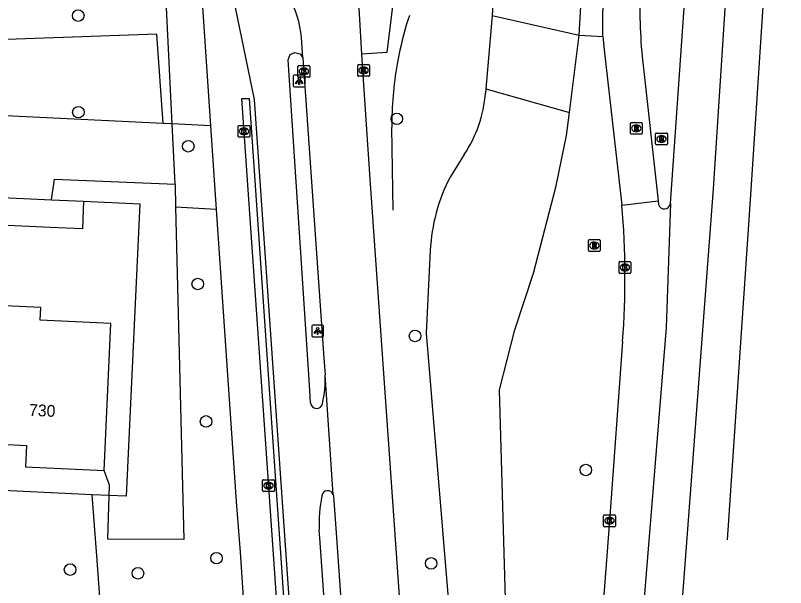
# Model space of a CAD drawing. Extents: x 161253 to 161848, y 384872 to 385383.
# Drawn here: x 161781 to 161846.3, y 385306.2 to 385354.7 of the extents above; entities that cross this region are included whole.
import ezdxf

# ---------------------------------------------------------------- set-up
doc = ezdxf.new("R2010")
doc.units = 0
for name, color, linetype in [('IMGEO_Berm_groen', 7, 'Continuous'), ('IMGEO_Boom', 7, 'Continuous'), ('IMGEO_Fietspad_open', 7, 'Continuous'), ('IMGEO_Groenvoorziening', 7, 'Continuous'), ('IMGEO_Hek', 7, 'Continuous'), ('IMGEO_Kolk', 7, 'Continuous'), ('IMGEO_Lichtpunt', 7, 'Continuous'), ('IMGEO_Muur', 7, 'Continuous'), ('IMGEO_Pand', 7, 'Continuous'), ('IMGEO_Pand_nummerreeks', 7, 'Continuous'), ('IMGEO_Rijbaan_lokaal_open', 7, 'Continuous'), ('IMGEO_Rijbaan_regionaal_gesloten', 7, 'Continuous'), ('IMGEO_Rioolput', 7, 'Continuous'), ('IMGEO_Voetpad_open', 7, 'Continuous')]:
    doc.layers.add(name, color=color, linetype=linetype)

msp = doc.modelspace()

# ---------------------------------------------------------------- linework, layer by layer
at = {"layer": 'IMGEO_Berm_groen'}
for points in [[(161820.751, 385357.276), (161820.788, 385357.005), (161821.547, 385357.044), (161821.412, 385354.663)], [(161821.412, 385354.663), (161820.884, 385348.462)], [(161821.412, 385354.663), (161828.775, 385352.994)], [(161827.957, 385346.444), (161828.775, 385352.994)], [(161820.884, 385348.462), (161820.852, 385348.089)], [(161820.884, 385348.462), (161827.957, 385346.444)], [(161816.166, 385334.74), (161815.82, 385327.746), (161822.257, 385250), (161823.001, 385241.01), (161823.031, 385250), (161823.145, 385284.452), (161822.02, 385322.916), (161823.326, 385328.009), (161824.925, 385332.823), (161826.852, 385340.216), (161827.714, 385344.496), (161827.957, 385346.444)], [(161819.046, 385342.871), (161817.837, 385340.968)]]:
    msp.add_lwpolyline(points, dxfattribs=at)
for centre, radius, start, end in [((161809.645, 385349.046), 11.248, 326.70052, 355.11703), ((161831.326, 385334.011), 15.178, 152.71653, 177.2455)]:
    msp.add_arc(centre, radius, start, end, dxfattribs=at)
at = {"layer": 'IMGEO_Boom'}
for centre in [(161786.31, 385354.662), (161786.323, 385346.475), (161813.332, 385345.903), (161795.642, 385343.583), (161796.445, 385331.904), (161814.873, 385327.495), (161797.146, 385320.249), (161829.357, 385316.131), (161798.038, 385308.659), (161816.236, 385308.211), (161785.619, 385307.682), (161791.373, 385307.373)]:
    msp.add_circle(centre, 0.489, dxfattribs=at)
at = {"layer": 'IMGEO_Fietspad_open'}
for points in [[(161799.416, 385136.747), (161804.851, 385161.932), (161805.798, 385165.717), (161808.364, 385173.407), (161809.023, 385177.396), (161809.973, 385187.32), (161810.725, 385197.446), (161810.795, 385201.149), (161811.014, 385207.171), (161808.054, 385250), (161801.247, 385347.561), (161799.482, 385356.188)], [(161806.008, 385321.812), (161805.94, 385322.912), (161804.115, 385350.912), (161804.294, 385351.353), (161804.687, 385351.542), (161805.133, 385351.414), (161805.369, 385351.08)], [(161806.85, 385157.128), (161812.029, 385175.625), (161814.159, 385203.908), (161813.652, 385212.427), (161806.814, 385309.979), (161806.751, 385311.045)]]:
    msp.add_lwpolyline(points, dxfattribs=at)
for centre, radius, start, end in [((161798.01, 385323.776), 9.239, 347.4358, 2.69956), ((161806.521, 385321.865), 0.516, 185.84527, 348.99038), ((161807.47, 385313.88), 0.496, 20.6567, 172.69349), ((161816.86, 385311.711), 10.131, 167.2724, 183.76995)]:
    msp.add_arc(centre, radius, start, end, dxfattribs=at)
at = {"layer": 'IMGEO_Groenvoorziening'}
for points in [[(161794.271, 385345.479), (161793.707, 385357.113)], [(161793.503, 385345.516), (161792.985, 385353.084), (161763.52, 385352.051), (161763.273, 385346.984)], [(161793.503, 385345.516), (161763.273, 385346.984)], [(161794.271, 385345.479), (161793.503, 385345.516)], [(161794.518, 385340.375), (161794.271, 385345.479)], [(161797.526, 385345.32), (161794.271, 385345.479)], [(161784.036, 385339.05), (161784.298, 385340.786), (161794.518, 385340.375)], [(161794.518, 385340.375), (161794.566, 385338.411)], [(161786.764, 385338.926), (161791.529, 385338.709), (161790.371, 385313.925), (161788.928, 385313.964)], [(161794.566, 385338.411), (161795.257, 385310.23), (161788.827, 385310.268), (161788.928, 385313.964)], [(161798.011, 385338.225), (161794.566, 385338.411)], [(161788.928, 385313.964), (161787.504, 385314.033)]]:
    msp.add_lwpolyline(points, dxfattribs=at)
at = {"layer": 'IMGEO_Hek'}
for points in [[(161813.495, 385351.313), (161813.349, 385350.542)], [(161813.007, 385338.149), (161812.908, 385345.182)], [(161784.036, 385339.05), (161784.298, 385340.786), (161794.518, 385340.375)], [(161794.518, 385340.375), (161794.566, 385338.411)], [(161794.566, 385338.411), (161795.257, 385310.23), (161788.827, 385310.268), (161788.928, 385313.964)], [(161788.928, 385313.964), (161788.952, 385314.831), (161788.498, 385316.088)]]:
    msp.add_lwpolyline(points, dxfattribs=at)
for centre, radius, start, end in [((161842.19, 385345.507), 29.276, 161.74486, 168.56194), ((161842.385, 385345.455), 29.478, 170.06258, 180.53046)]:
    msp.add_arc(centre, radius, start, end, dxfattribs=at)
at = {"layer": 'IMGEO_Kolk'}
for p, q in [((161804.945, 385349.501), (161804.945, 385350.353)), ((161805.02, 385350.427), (161805.872, 385350.427)), ((161805.433, 385350.207), (161805.458, 385350.207)), ((161805.946, 385350.353), (161805.946, 385349.501)), ((161810.007, 385349.586), (161810.007, 385350.438)), ((161810.082, 385350.512), (161810.934, 385350.512)), ((161810.495, 385350.292), (161810.52, 385350.292)), ((161811.008, 385350.438), (161811.008, 385349.586)), ((161805.456, 385349.647), (161805.431, 385349.647)), ((161810.518, 385349.732), (161810.493, 385349.732)), ((161805.872, 385349.427), (161805.02, 385349.427)), ((161810.934, 385349.512), (161810.082, 385349.512)), ((161799.866, 385344.421), (161799.866, 385345.273)), ((161799.941, 385345.347), (161800.793, 385345.347)), ((161800.354, 385345.127), (161800.379, 385345.127)), ((161800.867, 385345.273), (161800.867, 385344.421)), ((161800.793, 385344.347), (161799.941, 385344.347)), ((161800.377, 385344.567), (161800.352, 385344.567)), ((161832.167, 385332.875), (161832.167, 385333.727)), ((161832.242, 385333.801), (161833.094, 385333.801)), ((161832.655, 385333.581), (161832.68, 385333.581)), ((161833.168, 385333.727), (161833.168, 385332.875)), ((161833.094, 385332.801), (161832.242, 385332.801)), ((161832.678, 385333.021), (161832.653, 385333.021)), ((161801.943, 385314.383), (161801.943, 385315.235)), ((161802.018, 385315.309), (161802.87, 385315.309)), ((161802.431, 385315.089), (161802.456, 385315.089)), ((161802.944, 385315.235), (161802.944, 385314.383)), ((161802.87, 385314.309), (161802.018, 385314.309)), ((161802.454, 385314.529), (161802.429, 385314.529)), ((161830.932, 385312.324), (161831.784, 385312.324)), ((161830.857, 385311.398), (161830.857, 385312.25)), ((161831.345, 385312.104), (161831.37, 385312.104)), ((161831.858, 385312.25), (161831.858, 385311.398)), ((161831.784, 385311.324), (161830.932, 385311.324)), ((161831.368, 385311.544), (161831.343, 385311.544))]:
    msp.add_line(p, q, dxfattribs=at)
for points in [[(161804.945, 385349.501), (161804.945, 385350.353)], [(161805.02, 385350.427), (161805.872, 385350.427)], [(161805.946, 385350.353), (161805.946, 385349.501)], [(161810.007, 385349.586), (161810.007, 385350.438)], [(161810.082, 385350.512), (161810.934, 385350.512)], [(161810.328, 385350.212), (161810.451, 385350.212), (161810.451, 385350.061), (161810.581, 385350.212), (161810.745, 385350.212), (161810.599, 385350.061), (161810.752, 385349.812), (161810.6, 385349.812), (161810.515, 385349.976), (161810.451, 385349.909), (161810.451, 385349.812), (161810.328, 385349.812), (161810.328, 385350.212)], [(161811.008, 385350.438), (161811.008, 385349.586)], [(161805.266, 385350.127), (161805.389, 385350.127), (161805.389, 385349.976), (161805.519, 385350.127), (161805.683, 385350.127), (161805.537, 385349.976), (161805.69, 385349.727), (161805.538, 385349.727), (161805.453, 385349.891), (161805.389, 385349.824), (161805.389, 385349.727), (161805.266, 385349.727), (161805.266, 385350.127)], [(161805.872, 385349.427), (161805.02, 385349.427)], [(161810.934, 385349.512), (161810.082, 385349.512)], [(161799.866, 385344.421), (161799.866, 385345.273)], [(161799.941, 385345.347), (161800.793, 385345.347)], [(161800.187, 385345.047), (161800.31, 385345.047), (161800.31, 385344.896), (161800.44, 385345.047), (161800.604, 385345.047), (161800.458, 385344.896), (161800.611, 385344.647), (161800.459, 385344.647), (161800.374, 385344.811), (161800.31, 385344.744), (161800.31, 385344.647), (161800.187, 385344.647), (161800.187, 385345.047)], [(161800.867, 385345.273), (161800.867, 385344.421)], [(161800.793, 385344.347), (161799.941, 385344.347)], [(161832.167, 385332.875), (161832.167, 385333.727)], [(161832.242, 385333.801), (161833.094, 385333.801)], [(161832.488, 385333.501), (161832.611, 385333.501), (161832.611, 385333.35), (161832.741, 385333.501), (161832.905, 385333.501), (161832.759, 385333.35), (161832.912, 385333.101), (161832.76, 385333.101), (161832.675, 385333.265), (161832.611, 385333.198), (161832.611, 385333.101), (161832.488, 385333.101), (161832.488, 385333.501)], [(161833.168, 385333.727), (161833.168, 385332.875)], [(161833.094, 385332.801), (161832.242, 385332.801)], [(161801.943, 385314.383), (161801.943, 385315.235)], [(161802.018, 385315.309), (161802.87, 385315.309)], [(161802.264, 385315.009), (161802.387, 385315.009), (161802.387, 385314.858), (161802.517, 385315.009), (161802.681, 385315.009), (161802.535, 385314.858), (161802.688, 385314.609), (161802.536, 385314.609), (161802.451, 385314.773), (161802.387, 385314.706), (161802.387, 385314.609), (161802.264, 385314.609), (161802.264, 385315.009)], [(161802.944, 385315.235), (161802.944, 385314.383)], [(161802.87, 385314.309), (161802.018, 385314.309)], [(161830.932, 385312.324), (161831.784, 385312.324)], [(161830.857, 385311.398), (161830.857, 385312.25)], [(161831.178, 385312.024), (161831.301, 385312.024), (161831.301, 385311.873), (161831.431, 385312.024), (161831.595, 385312.024), (161831.449, 385311.873), (161831.602, 385311.624), (161831.45, 385311.624), (161831.365, 385311.788), (161831.301, 385311.721), (161831.301, 385311.624), (161831.178, 385311.624), (161831.178, 385312.024)], [(161831.858, 385312.25), (161831.858, 385311.398)], [(161831.784, 385311.324), (161830.932, 385311.324)]]:
    msp.add_lwpolyline(points, dxfattribs=at)
for centre, start, end in [((161805.022, 385350.351), 91.55205, 178.44795), ((161805.022, 385350.351), 91.55205, 178.44795), ((161805.87, 385350.351), 1.55205, 88.44795), ((161805.87, 385350.351), 1.55205, 88.44795), ((161810.084, 385350.436), 91.55205, 178.44795), ((161810.084, 385350.436), 91.55205, 178.44795), ((161810.932, 385350.436), 1.55205, 88.44795), ((161810.932, 385350.436), 1.55205, 88.44795), ((161810.084, 385349.588), 181.55205, 268.44795), ((161810.084, 385349.588), 181.55205, 268.44795), ((161810.932, 385349.588), 271.55205, 358.44795), ((161810.932, 385349.588), 271.55205, 358.44795), ((161805.022, 385349.503), 181.55205, 268.44795), ((161805.022, 385349.503), 181.55205, 268.44795), ((161805.87, 385349.503), 271.55205, 358.44795), ((161805.87, 385349.503), 271.55205, 358.44795), ((161799.943, 385345.271), 91.55205, 178.44795), ((161799.943, 385345.271), 91.55205, 178.44795), ((161800.791, 385345.271), 1.55205, 88.44795), ((161800.791, 385345.271), 1.55205, 88.44795), ((161799.943, 385344.423), 181.55205, 268.44795), ((161799.943, 385344.423), 181.55205, 268.44795), ((161800.791, 385344.423), 271.55205, 358.44795), ((161800.791, 385344.423), 271.55205, 358.44795), ((161832.244, 385333.725), 91.55205, 178.44795), ((161832.244, 385333.725), 91.55205, 178.44795), ((161833.092, 385333.725), 1.55205, 88.44795), ((161833.092, 385333.725), 1.55205, 88.44795), ((161832.244, 385332.877), 181.55205, 268.44795), ((161832.244, 385332.877), 181.55205, 268.44795), ((161833.092, 385332.877), 271.55205, 358.44795), ((161833.092, 385332.877), 271.55205, 358.44795), ((161802.02, 385315.233), 91.55205, 178.44795), ((161802.02, 385315.233), 91.55205, 178.44795), ((161802.868, 385315.233), 1.55205, 88.44795), ((161802.868, 385315.233), 1.55205, 88.44795), ((161802.02, 385314.385), 181.55205, 268.44795), ((161802.02, 385314.385), 181.55205, 268.44795), ((161802.868, 385314.385), 271.55205, 358.44795), ((161802.868, 385314.385), 271.55205, 358.44795), ((161830.934, 385312.248), 91.55205, 178.44795), ((161830.934, 385312.248), 91.55205, 178.44795), ((161831.782, 385312.248), 1.55205, 88.44795), ((161831.782, 385312.248), 1.55205, 88.44795), ((161830.934, 385311.4), 181.55205, 268.44795), ((161830.934, 385311.4), 181.55205, 268.44795), ((161831.782, 385311.4), 271.55205, 358.44795), ((161831.782, 385311.4), 271.55205, 358.44795)]:
    msp.add_arc(centre, 0.0765, start, end, dxfattribs=at)
for centre, major_axis, ratio, start_param, end_param in [((161805.432, 385349.927), (-0.387, 0.002), 0.722429, 4.712389, 7.853982), ((161805.457, 385349.927), (-0.39, 0.002), 0.717154, 1.570796, 4.712389), ((161810.494, 385350.012), (-0.387, 0.002), 0.722429, 4.712389, 7.853982), ((161810.519, 385350.012), (-0.39, 0.002), 0.717154, 1.570796, 4.712389), ((161800.353, 385344.847), (-0.387, 0.002), 0.722429, 4.712389, 7.853982), ((161800.378, 385344.847), (-0.39, 0.002), 0.717154, 1.570796, 4.712389), ((161832.654, 385333.301), (-0.387, 0.002), 0.722429, 4.712389, 7.853982), ((161832.679, 385333.301), (-0.39, 0.002), 0.717154, 1.570796, 4.712389), ((161802.43, 385314.809), (-0.387, 0.002), 0.722429, 4.712389, 7.853982), ((161802.455, 385314.809), (-0.39, 0.002), 0.717154, 1.570796, 4.712389), ((161831.344, 385311.824), (-0.387, 0.002), 0.722429, 4.712389, 7.853982), ((161831.369, 385311.824), (-0.39, 0.002), 0.717154, 1.570796, 4.712389)]:
    msp.add_ellipse(centre, major_axis=major_axis, ratio=ratio, start_param=start_param, end_param=end_param, dxfattribs=at)
at = {"layer": 'IMGEO_Lichtpunt'}
for p, q in [((161805.451, 385349.607), (161804.643, 385349.607)), ((161805.451, 385349.607), (161804.643, 385349.607)), ((161804.549, 385349.512), (161804.549, 385348.705)), ((161804.549, 385349.512), (161804.549, 385348.705)), ((161805.545, 385348.705), (161805.545, 385349.512)), ((161805.545, 385348.705), (161805.545, 385349.512)), ((161804.643, 385348.611), (161805.451, 385348.611)), ((161804.643, 385348.611), (161805.451, 385348.611)), ((161806.117, 385328.329), (161806.117, 385327.522)), ((161806.117, 385328.329), (161806.117, 385327.522)), ((161807.019, 385328.424), (161806.211, 385328.424)), ((161807.019, 385328.424), (161806.211, 385328.424)), ((161807.113, 385327.522), (161807.113, 385328.329)), ((161807.113, 385327.522), (161807.113, 385328.329)), ((161806.211, 385327.428), (161807.019, 385327.428)), ((161806.211, 385327.428), (161807.019, 385327.428))]:
    msp.add_line(p, q, dxfattribs=at)
for points in [[(161804.923, 385349.176), (161804.962, 385349.148), (161804.774, 385348.886), (161804.736, 385348.913), (161804.923, 385349.176)], [(161805.025, 385349.128), (161805.072, 385349.128), (161805.072, 385348.806), (161805.025, 385348.806), (161805.025, 385349.128)], [(161805.135, 385349.148), (161805.173, 385349.175), (161805.36, 385348.913), (161805.321, 385348.885), (161805.135, 385349.148)], [(161806.491, 385327.993), (161806.53, 385327.965), (161806.342, 385327.703), (161806.304, 385327.73), (161806.491, 385327.993)], [(161806.703, 385327.965), (161806.741, 385327.992), (161806.928, 385327.73), (161806.889, 385327.702), (161806.703, 385327.965)], [(161806.593, 385327.945), (161806.64, 385327.945), (161806.64, 385327.623), (161806.593, 385327.623), (161806.593, 385327.945)]]:
    msp.add_lwpolyline(points, dxfattribs=at)
for centre in [(161805.048, 385349.31), (161806.616, 385328.127)]:
    msp.add_circle(centre, 0.0994, dxfattribs=at)
for centre, start, end in [((161804.643, 385349.512), 90, 180), ((161804.643, 385349.512), 90, 180), ((161805.451, 385349.512), 0, 90), ((161805.451, 385349.512), 0, 90), ((161804.643, 385348.705), 180, 270), ((161804.643, 385348.705), 180, 270), ((161805.451, 385348.705), 270, 0), ((161805.451, 385348.705), 270, 360), ((161806.211, 385328.329), 90, 180), ((161806.211, 385328.329), 90, 180), ((161807.019, 385328.329), 0, 90), ((161807.019, 385328.329), 0, 90), ((161806.211, 385327.522), 180, 270), ((161806.211, 385327.522), 180, 270), ((161807.019, 385327.522), 270, 0), ((161807.019, 385327.522), 270, 360)]:
    msp.add_arc(centre, 0.0946, start, end, dxfattribs=at)
at = {"layer": 'IMGEO_Muur'}
msp.add_lwpolyline([(161809.266, 385191.488), (161809.957, 385207.224), (161806.977, 385250), (161800.175, 385347.621), (161800.798, 385347.634), (161807.52, 385250), (161810.465, 385207.275), (161809.778, 385192.126), (161808.589, 385177.868), (161808.119, 385177.946)], dxfattribs=at)
at = {"layer": 'IMGEO_Pand'}
for points in [[(161779.237, 385339.268), (161784.036, 385339.05)], [(161786.764, 385338.926), (161786.658, 385336.573), (161783.93, 385336.696), (161779.117, 385336.914)], [(161784.036, 385339.05), (161786.764, 385338.926)], [(161778.178, 385318.394), (161781.911, 385318.22), (161781.826, 385316.4), (161788.498, 385316.088), (161789.079, 385328.549), (161783.08, 385328.829), (161783.131, 385329.911), (161778.88, 385330.109), (161778.733, 385326.946), (161778.612, 385326.952)]]:
    msp.add_lwpolyline(points, dxfattribs=at)
at = {"layer": 'IMGEO_Rijbaan_lokaal_open'}
for points in [[(161830.805, 385352.903), (161830.796, 385354.908), (161830.841, 385355.738), (161830.948, 385357.532), (161831.064, 385359.484), (161831.194, 385361.662), (161831.255, 385362.69), (161831.469, 385366.284), (161831.665, 385369.572), (161831.718, 385370.476), (161831.736, 385370.773), (161832.059, 385376.203), (161832.368, 385380.807), (161832.388, 385381.111), (161832.439, 385381.868), (161832.509, 385382.906)], [(161830.805, 385352.903), (161830.939, 385351.516), (161832.415, 385338.59)], [(161834.125, 385351.188), (161835.492, 385338.948)]]:
    msp.add_lwpolyline(points, dxfattribs=at)
msp.add_arc((161879.572, 385355.321), 45.635, 177.02342, 185.19659, dxfattribs=at)
at = {"layer": 'IMGEO_Rijbaan_regionaal_gesloten'}
for points in [[(161843.005, 385383.208), (161841.331, 385358.305), (161840.149, 385339.983), (161835.302, 385275.534), (161832.26, 385245.433), (161832.129, 385244.136), (161827.354, 385207.649), (161824.158, 385190.185), (161821.142, 385173.699), (161813.159, 385133.822)], [(161836.528, 385338.731), (161837.794, 385356.966), (161837.857, 385357.892), (161837.879, 385358.218), (161837.989, 385359.837), (161838.137, 385362.021), (161838.207, 385363.042), (161838.446, 385366.578), (161838.674, 385369.936), (161838.735, 385370.829), (161839.432, 385381.161), (161839.452, 385381.464), (161839.504, 385382.247), (161839.562, 385383.109)], [(161841.361, 385310.203), (161843.332, 385339.452), (161844.588, 385358.474), (161846.294, 385383.303)], [(161810.363, 385351.383), (161810.086, 385356.298)], [(161805.369, 385351.08), (161805.249, 385352.81)], [(161805.369, 385351.08), (161807.138, 385325.616), (161807.239, 385324.211)], [(161820.763, 385202.038), (161819.519, 385220.338), (161818.054, 385241.62), (161817.448, 385250), (161811.078, 385340.796), (161810.451, 385350.052), (161810.363, 385351.383)], [(161836.528, 385338.731), (161836.173, 385328.205), (161830.26, 385255.555), (161825.195, 385215.738), (161824.131, 385211.474)], [(161832.415, 385338.59), (161835.492, 385338.948)], [(161835.492, 385338.948), (161835.518, 385338.649)], [(161832.467, 385327.037), (161831.359, 385311.824), (161829.723, 385290.378), (161828.725, 385278.097), (161828.314, 385273.073), (161826.86, 385257.604), (161826.033, 385250), (161825.773, 385247.608), (161825.632, 385244.355), (161824.63, 385221.78), (161824.131, 385211.474)], [(161807.935, 385314.055), (161807.239, 385324.211)], [(161807.935, 385314.055), (161807.968, 385313.899), (161808.13, 385311.584), (161815.94, 385200.171)]]:
    msp.add_lwpolyline(points, dxfattribs=at)
for centre, radius, start, end in [((161796.346, 385351.966), 8.942, 5.41542, 52.2838), ((161760.644, 385332.49), 72.03, 355.65801, 4.85776), ((161836.016, 385338.78), 0.515, 194.74454, 354.53857)]:
    msp.add_arc(centre, radius, start, end, dxfattribs=at)
at = {"layer": 'IMGEO_Rioolput'}
for p, q in [((161833.135, 385344.678), (161833.135, 385345.53)), ((161833.21, 385345.604), (161834.062, 385345.604)), ((161833.623, 385345.384), (161833.648, 385345.384)), ((161834.136, 385345.53), (161834.136, 385344.678)), ((161834.062, 385344.604), (161833.21, 385344.604)), ((161833.646, 385344.824), (161833.621, 385344.824)), ((161835.265, 385343.778), (161835.265, 385344.63)), ((161835.34, 385344.704), (161836.192, 385344.704)), ((161835.753, 385344.484), (161835.778, 385344.484)), ((161836.266, 385344.63), (161836.266, 385343.778)), ((161836.192, 385343.704), (161835.34, 385343.704)), ((161835.776, 385343.924), (161835.751, 385343.924)), ((161829.573, 385334.74), (161829.573, 385335.592)), ((161829.648, 385335.666), (161830.5, 385335.666)), ((161830.061, 385335.446), (161830.086, 385335.446)), ((161830.574, 385335.592), (161830.574, 385334.74)), ((161830.5, 385334.666), (161829.648, 385334.666)), ((161830.084, 385334.886), (161830.059, 385334.886))]:
    msp.add_line(p, q, dxfattribs=at)
for points in [[(161833.135, 385344.678), (161833.135, 385345.53)], [(161833.21, 385345.604), (161834.062, 385345.604)], [(161833.724, 385345.302), (161833.472, 385345.304), (161833.472, 385344.904)], [(161833.472, 385344.904), (161833.596, 385344.904), (161833.596, 385345.066), (161833.607, 385345.066)], [(161833.65, 385345.223), (161833.596, 385345.223), (161833.596, 385345.142)], [(161833.596, 385345.142), (161833.648, 385345.142)], [(161833.654, 385345.037), (161833.725, 385344.904), (161833.865, 385344.904), (161833.8, 385345.03)], [(161834.136, 385345.53), (161834.136, 385344.678)], [(161834.062, 385344.604), (161833.21, 385344.604)], [(161835.265, 385343.778), (161835.265, 385344.63)], [(161835.34, 385344.704), (161836.192, 385344.704)], [(161835.854, 385344.402), (161835.602, 385344.404), (161835.602, 385344.004)], [(161835.78, 385344.323), (161835.726, 385344.323), (161835.726, 385344.242)], [(161836.266, 385344.63), (161836.266, 385343.778)], [(161836.192, 385343.704), (161835.34, 385343.704)], [(161835.602, 385344.004), (161835.726, 385344.004), (161835.726, 385344.166), (161835.737, 385344.166)], [(161835.726, 385344.242), (161835.778, 385344.242)], [(161835.784, 385344.137), (161835.855, 385344.004), (161835.995, 385344.004), (161835.93, 385344.13)], [(161829.573, 385334.74), (161829.573, 385335.592)], [(161829.648, 385335.666), (161830.5, 385335.666)], [(161830.162, 385335.364), (161829.91, 385335.366), (161829.91, 385334.966)], [(161830.088, 385335.285), (161830.034, 385335.285), (161830.034, 385335.204)], [(161830.034, 385335.204), (161830.086, 385335.204)], [(161830.574, 385335.592), (161830.574, 385334.74)], [(161830.5, 385334.666), (161829.648, 385334.666)], [(161829.91, 385334.966), (161830.034, 385334.966), (161830.034, 385335.128), (161830.045, 385335.128)], [(161830.092, 385335.099), (161830.163, 385334.966), (161830.303, 385334.966), (161830.238, 385335.092)]]:
    msp.add_lwpolyline(points, dxfattribs=at)
for centre, radius, start, end in [((161833.212, 385345.528), 0.0765, 91.55205, 178.44795), ((161833.212, 385345.528), 0.0765, 91.55205, 178.44795), ((161833.606, 385345.013), 0.0533, 26.02933, 88.69889), ((161833.632, 385345.331), 0.19, 274.7715, 282.96867), ((161833.656, 385345.127), 0.0964, 77.00612, 93.18647), ((161833.67, 385345.184), 0.0378, 276.66336, 79.67722), ((161833.723, 385345.192), 0.109, 350.36119, 89.41601), ((161833.721, 385345.192), 0.112, 277.58423, 350.98172), ((161833.705, 385344.977), 0.108, 29.51342, 73.79051), ((161834.06, 385345.528), 0.0765, 1.55205, 88.44795), ((161834.06, 385345.528), 0.0765, 1.55205, 88.44795), ((161833.212, 385344.68), 0.0765, 181.55205, 268.44795), ((161833.212, 385344.68), 0.0765, 181.55205, 268.44795), ((161834.06, 385344.68), 0.0765, 271.55205, 358.44795), ((161834.06, 385344.68), 0.0765, 271.55205, 358.44795), ((161835.342, 385344.628), 0.0765, 91.55205, 178.44795), ((161835.342, 385344.628), 0.0765, 91.55205, 178.44795), ((161835.786, 385344.227), 0.0964, 77.00612, 93.18647), ((161835.8, 385344.284), 0.0378, 276.66336, 79.67722), ((161835.853, 385344.292), 0.109, 350.36119, 89.41601), ((161836.19, 385344.628), 0.0765, 1.55205, 88.44795), ((161836.19, 385344.628), 0.0765, 1.55205, 88.44795), ((161835.342, 385343.78), 0.0765, 181.55205, 268.44795), ((161835.342, 385343.78), 0.0765, 181.55205, 268.44795), ((161835.736, 385344.113), 0.0533, 26.02933, 88.69889), ((161835.762, 385344.431), 0.19, 274.7715, 282.96867), ((161835.851, 385344.292), 0.112, 277.58423, 350.98172), ((161835.835, 385344.077), 0.108, 29.51342, 73.79051), ((161836.19, 385343.78), 0.0765, 271.55205, 358.44795), ((161836.19, 385343.78), 0.0765, 271.55205, 358.44795), ((161829.65, 385335.59), 0.0765, 91.55205, 178.44795), ((161829.65, 385335.59), 0.0765, 91.55205, 178.44795), ((161830.07, 385335.393), 0.19, 274.7715, 282.96867), ((161830.094, 385335.189), 0.0964, 77.00612, 93.18647), ((161830.108, 385335.246), 0.0378, 276.66336, 79.67722), ((161830.161, 385335.254), 0.109, 350.36119, 89.41601), ((161830.159, 385335.254), 0.112, 277.58423, 350.98172), ((161830.498, 385335.59), 0.0765, 1.55205, 88.44795), ((161830.498, 385335.59), 0.0765, 1.55205, 88.44795), ((161829.65, 385334.742), 0.0765, 181.55205, 268.44795), ((161829.65, 385334.742), 0.0765, 181.55205, 268.44795), ((161830.044, 385335.075), 0.0533, 26.02933, 88.69889), ((161830.143, 385335.039), 0.108, 29.51342, 73.79051), ((161830.498, 385334.742), 0.0765, 271.55205, 358.44795), ((161830.498, 385334.742), 0.0765, 271.55205, 358.44795)]:
    msp.add_arc(centre, radius, start, end, dxfattribs=at)
for centre, major_axis, ratio, start_param, end_param in [((161833.622, 385345.104), (-0.387, 0.002), 0.722429, 4.712389, 7.853982), ((161833.647, 385345.104), (-0.39, 0.002), 0.717154, 1.570796, 4.712389), ((161835.752, 385344.204), (-0.387, 0.002), 0.722429, 4.712389, 7.853982), ((161835.777, 385344.204), (-0.39, 0.002), 0.717154, 1.570796, 4.712389), ((161830.06, 385335.166), (-0.387, 0.002), 0.722429, 4.712389, 7.853982), ((161830.085, 385335.166), (-0.39, 0.002), 0.717154, 1.570796, 4.712389)]:
    msp.add_ellipse(centre, major_axis=major_axis, ratio=ratio, start_param=start_param, end_param=end_param, dxfattribs=at)
at = {"layer": 'IMGEO_Voetpad_open'}
for points in [[(161828.775, 385352.994), (161829.055, 385357.434), (161829.179, 385359.388), (161829.317, 385361.564), (161829.382, 385362.595), (161829.611, 385366.215), (161829.818, 385369.474), (161829.875, 385370.383), (161829.894, 385370.681), (161830.23, 385375.958), (161830.558, 385380.716), (161830.579, 385381.02), (161830.631, 385381.771), (161830.706, 385382.854)], [(161796.807, 385355.822), (161797.526, 385345.32)], [(161812.969, 385355.46), (161812.468, 385351.533), (161810.363, 385351.383)], [(161828.775, 385352.994), (161829.262, 385352.972), (161829.794, 385352.948), (161830.805, 385352.903)], [(161797.526, 385345.32), (161798.011, 385338.225)], [(161798.011, 385338.225), (161799.707, 385313.446), (161800.036, 385309.166), (161801.504, 385286.924)], [(161787.504, 385314.033), (161759.56, 385315.378)], [(161788.455, 385301.124), (161787.886, 385308.846), (161787.504, 385314.033)]]:
    msp.add_lwpolyline(points, dxfattribs=at)

# ---------------------------------------------------------------- texts
at = {"layer": 'IMGEO_Pand_nummerreeks'}
msp.add_text('730', height=1, rotation=357.33002, dxfattribs=at).set_placement((161782.123, 385320.733))

doc.saveas('drawing.dxf')
